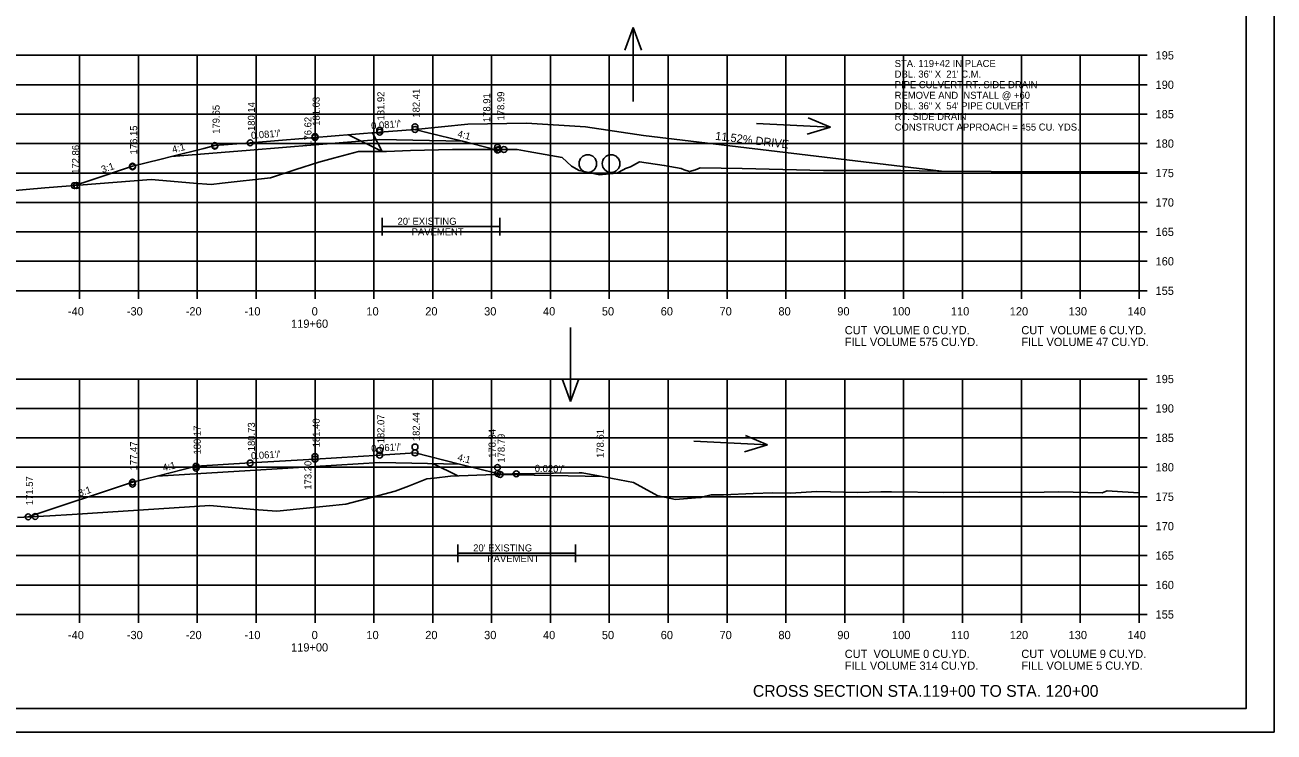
# Model space of a CAD drawing. Extents: x 915787 to 919910, y 133456 to 136717.
# Drawn here: x 916364.7 to 916576.9, y 135802.7 to 135922.9 of the extents above; entities that cross this region are included whole.
import ezdxf

# ---------------------------------------------------------------- set-up
doc = ezdxf.new("R2010")
doc.units = 0
for name, color, linetype in [('R_Axis', 7, 'Continuous'), ('R_Axis Annot', 7, 'Continuous'), ('R_Border', 7, 'Continuous'), ('R_Border Notes', 7, 'Continuous'), ('R_Draft', 7, 'Continuous'), ('R_Drive', 7, 'Continuous'), ('R_Exist Surface', 7, 'Continuous'), ('R_Exist Surface Annot', 7, 'Continuous'), ('R_Fin Surface', 7, 'Continuous'), ('R_Grid', 7, 'Continuous'), ('R_No Plot', 7, 'Continuous'), ('R_Water', 7, 'Continuous'), ('R_Water Annot', 7, 'Continuous'), ('R_Xsect Elev', 7, 'Continuous'), ('R_Xsect Slope', 7, 'Continuous')]:
    doc.layers.add(name, color=color, linetype=linetype)

msp = doc.modelspace()

# ---------------------------------------------------------------- linework, layer by layer
at = {"layer": 'R_Axis'}
for p, q in [((916553.98, 135877.73), (916553.98, 135917.73)), ((916555.38, 135917.73), (916553.98, 135917.73)), ((916555.38, 135912.73), (916553.98, 135912.73)), ((916555.38, 135907.73), (916553.98, 135907.73)), ((916555.38, 135902.73), (916553.98, 135902.73)), ((916555.38, 135897.73), (916553.98, 135897.73)), ((916555.38, 135892.73), (916553.98, 135892.73)), ((916555.38, 135887.73), (916553.98, 135887.73)), ((916555.38, 135882.73), (916553.98, 135882.73)), ((916273.98, 135877.73), (916553.98, 135877.73)), ((916373.98, 135876.33), (916373.98, 135877.73)), ((916383.98, 135876.33), (916383.98, 135877.73)), ((916393.98, 135876.33), (916393.98, 135877.73)), ((916403.98, 135876.33), (916403.98, 135877.73)), ((916413.98, 135876.33), (916413.98, 135877.73)), ((916423.98, 135876.33), (916423.98, 135877.73)), ((916433.98, 135876.33), (916433.98, 135877.73)), ((916443.98, 135876.33), (916443.98, 135877.73)), ((916453.98, 135876.33), (916453.98, 135877.73)), ((916463.98, 135876.33), (916463.98, 135877.73)), ((916473.98, 135876.33), (916473.98, 135877.73)), ((916483.98, 135876.33), (916483.98, 135877.73)), ((916493.98, 135876.33), (916493.98, 135877.73)), ((916503.98, 135876.33), (916503.98, 135877.73)), ((916513.98, 135876.33), (916513.98, 135877.73)), ((916523.98, 135876.33), (916523.98, 135877.73)), ((916533.98, 135876.33), (916533.98, 135877.73)), ((916543.98, 135876.33), (916543.98, 135877.73)), ((916553.98, 135876.33), (916553.98, 135877.73)), ((916555.38, 135877.73), (916553.98, 135877.73)), ((916553.98, 135822.73), (916553.98, 135862.73)), ((916555.38, 135862.73), (916553.98, 135862.73)), ((916555.38, 135857.73), (916553.98, 135857.73)), ((916555.38, 135852.73), (916553.98, 135852.73)), ((916555.38, 135847.73), (916553.98, 135847.73)), ((916555.38, 135842.73), (916553.98, 135842.73)), ((916555.38, 135837.73), (916553.98, 135837.73)), ((916555.38, 135832.73), (916553.98, 135832.73)), ((916555.38, 135827.73), (916553.98, 135827.73)), ((916273.98, 135822.73), (916553.98, 135822.73)), ((916373.98, 135821.33), (916373.98, 135822.73)), ((916383.98, 135821.33), (916383.98, 135822.73)), ((916393.98, 135821.33), (916393.98, 135822.73)), ((916403.98, 135821.33), (916403.98, 135822.73)), ((916413.98, 135821.33), (916413.98, 135822.73)), ((916423.98, 135821.33), (916423.98, 135822.73)), ((916433.98, 135821.33), (916433.98, 135822.73)), ((916443.98, 135821.33), (916443.98, 135822.73)), ((916453.98, 135821.33), (916453.98, 135822.73)), ((916463.98, 135821.33), (916463.98, 135822.73)), ((916473.98, 135821.33), (916473.98, 135822.73)), ((916483.98, 135821.33), (916483.98, 135822.73)), ((916493.98, 135821.33), (916493.98, 135822.73)), ((916503.98, 135821.33), (916503.98, 135822.73)), ((916513.98, 135821.33), (916513.98, 135822.73)), ((916523.98, 135821.33), (916523.98, 135822.73)), ((916533.98, 135821.33), (916533.98, 135822.73)), ((916543.98, 135821.33), (916543.98, 135822.73)), ((916553.98, 135821.33), (916553.98, 135822.73)), ((916555.38, 135822.73), (916553.98, 135822.73))]:
    msp.add_line(p, q, dxfattribs=at)
at = {"layer": 'R_Border'}
for q in [(916572.16, 136012.19), (916255.98, 135806.73)]:
    msp.add_line((916572.16, 135806.73), q, dxfattribs=at)
at = {"layer": 'R_Drive'}
for p, q in [((916439.93, 135906.01), (916430.97, 135905.14)), ((916449.93, 135906.18), (916439.93, 135906.01)), ((916459.91, 135905.56), (916449.93, 135906.18)), ((916469.81, 135904.13), (916459.91, 135905.56)), ((916419.68, 135904.22), (916425.36, 135901.38)), ((916469.81, 135904.13), (916520.4, 135898.06)), ((916434, 135848.37), (916438.22, 135846.26))]:
    msp.add_line(p, q, dxfattribs=at)
at = {"layer": 'R_Exist Surface'}
for points in [[(916361.71, 135894.67), (916368.05, 135895.2), (916386.14, 135896.62), (916393.36, 135896), (916396.31, 135895.77), (916398.21, 135895.98), (916406.44, 135896.91), (916410.71, 135898.3), (916414.61, 135899.56), (916417.12, 135900.24), (916421.36, 135901.39), (916423.59, 135901.41), (916426.12, 135901.41), (916430.23, 135901.53), (916437.32, 135901.72), (916445.81, 135901.73), (916448.33, 135901.71), (916450.2, 135901.36), (916455.97, 135900.35), (916457.56, 135898.89), (916458.83, 135898.13), (916461.83, 135897.53), (916462.32, 135897.44), (916462.83, 135897.46), (916465.24, 135897.71), (916466.46, 135898.35), (916466.74, 135898.47), (916467.55, 135898.8), (916469.13, 135899.62), (916473.3, 135899.03), (916476.16, 135898.5), (916476.68, 135898.29), (916477.63, 135897.98), (916478.62, 135898.28), (916479.39, 135898.59), (916486.56, 135898.48), (916500.36, 135898.18), (916506.22, 135898.15), (916513.52, 135898.15), (916519.76, 135898.07), (916528.86, 135897.96), (916534.17, 135897.95), (916538.54, 135897.94), (916553.98, 135897.97)], [(916363.43, 135839.21), (916368.92, 135839.48), (916372.74, 135839.72), (916396.1, 135841.21), (916403.59, 135840.57), (916407.48, 135840.26), (916412.51, 135840.78), (916419.23, 135841.47), (916424.84, 135842.92), (916427.62, 135843.69), (916429.86, 135844.53), (916432.98, 135845.76), (916434.22, 135845.88), (916437.01, 135846.22), (916447.49, 135846.6), (916448.33, 135846.62), (916454.5, 135846.72), (916458.86, 135846.8), (916459.35, 135846.81), (916462.12, 135846.29), (916468.07, 135845.17), (916471.6, 135843.21), (916472.22, 135842.88), (916472.26, 135842.88), (916475.22, 135842.26), (916479.3, 135842.59), (916479.54, 135842.59), (916479.89, 135842.69), (916481.27, 135843.04), (916483.39, 135843.03), (916488.41, 135843.26), (916491.76, 135843.38), (916494.74, 135843.33), (916499.26, 135843.6), (916506.12, 135843.44), (916510.09, 135843.58), (916511.94, 135843.54), (916520.8, 135843.47), (916526.91, 135843.53), (916535.35, 135843.42), (916540.34, 135843.54), (916547.69, 135843.39), (916548.55, 135843.74), (916551.19, 135843.56), (916553.98, 135843.41)]]:
    msp.add_lwpolyline(points, dxfattribs=at)
at = {"layer": 'R_Exist Surface Annot'}
for p, q in [((916425.36, 135890.13), (916425.36, 135887.13)), ((916425.36, 135888.63), (916445.36, 135888.63)), ((916445.36, 135890.13), (916445.36, 135887.13)), ((916438.22, 135834.63), (916438.22, 135831.63)), ((916458.21, 135834.63), (916458.21, 135831.63)), ((916438.22, 135833.13), (916458.21, 135833.13))]:
    msp.add_line(p, q, dxfattribs=at)
at = {"layer": 'R_Fin Surface'}
for points in [[(916373.1, 135895.59), (916375.75, 135896.48), (916382.97, 135898.89), (916387.87, 135900.11), (916389.57, 135900.53), (916395.11, 135901.92), (916396.97, 135902.39), (916398.48, 135902.51), (916402.97, 135902.87), (916405.74, 135903.09), (916413.97, 135903.76), (916416.74, 135903.98), (916424.97, 135904.66), (916426.48, 135904.78), (916430.97, 135905.14), (916432.99, 135904.64), (916439.04, 135903.12), (916440.55, 135902.75), (916444.97, 135901.64), (916445.02, 135901.66), (916445.21, 135901.72)], [(916389.57, 135900.53), (916402.97, 135901.62), (916413.97, 135902.51), (916424.97, 135903.41), (916439.04, 135903.12)], [(916365.26, 135839.3), (916382.97, 135845.21), (916387.16, 135846.25), (916393.77, 135847.9), (916402.97, 135848.46), (916413.97, 135849.13), (916424.97, 135849.8), (916430.97, 135850.17), (916438.52, 135848.28), (916444.97, 135846.67), (916445.41, 135846.52), (916462.76, 135846.18)], [(916387.16, 135846.25), (916402.97, 135847.21), (916413.97, 135847.88), (916424.97, 135848.55), (916438.52, 135848.28)]]:
    msp.add_lwpolyline(points, dxfattribs=at)
at = {"layer": 'R_Grid'}
for p, q in [((916273.98, 135917.73), (916553.98, 135917.73)), ((916373.98, 135877.73), (916373.98, 135917.73)), ((916383.98, 135877.73), (916383.98, 135917.73)), ((916393.98, 135877.73), (916393.98, 135917.73)), ((916403.98, 135877.73), (916403.98, 135917.73)), ((916413.98, 135877.73), (916413.98, 135917.73)), ((916423.98, 135877.73), (916423.98, 135917.73)), ((916433.98, 135877.73), (916433.98, 135917.73)), ((916443.98, 135877.73), (916443.98, 135917.73)), ((916453.98, 135877.73), (916453.98, 135917.73)), ((916463.98, 135877.73), (916463.98, 135917.73)), ((916473.98, 135877.73), (916473.98, 135917.73)), ((916483.98, 135877.73), (916483.98, 135917.73)), ((916493.98, 135877.73), (916493.98, 135917.73)), ((916503.98, 135877.73), (916503.98, 135917.73)), ((916513.98, 135877.73), (916513.98, 135917.73)), ((916523.98, 135877.73), (916523.98, 135917.73)), ((916533.98, 135877.73), (916533.98, 135917.73)), ((916543.98, 135877.73), (916543.98, 135917.73)), ((916553.98, 135877.73), (916553.98, 135917.73)), ((916273.98, 135912.73), (916553.98, 135912.73)), ((916273.98, 135907.73), (916553.98, 135907.73)), ((916273.98, 135902.73), (916553.98, 135902.73)), ((916273.98, 135897.73), (916553.98, 135897.73)), ((916273.98, 135892.73), (916553.98, 135892.73)), ((916273.98, 135887.73), (916553.98, 135887.73)), ((916273.98, 135882.73), (916553.98, 135882.73)), ((916273.98, 135877.73), (916553.98, 135877.73)), ((916273.98, 135862.73), (916553.98, 135862.73)), ((916373.98, 135822.73), (916373.98, 135862.73)), ((916383.98, 135822.73), (916383.98, 135862.73)), ((916393.98, 135822.73), (916393.98, 135862.73)), ((916403.98, 135822.73), (916403.98, 135862.73)), ((916413.98, 135822.73), (916413.98, 135862.73)), ((916423.98, 135822.73), (916423.98, 135862.73)), ((916433.98, 135822.73), (916433.98, 135862.73)), ((916443.98, 135822.73), (916443.98, 135862.73)), ((916453.98, 135822.73), (916453.98, 135862.73)), ((916463.98, 135822.73), (916463.98, 135862.73)), ((916473.98, 135822.73), (916473.98, 135862.73)), ((916483.98, 135822.73), (916483.98, 135862.73)), ((916493.98, 135822.73), (916493.98, 135862.73)), ((916503.98, 135822.73), (916503.98, 135862.73)), ((916513.98, 135822.73), (916513.98, 135862.73)), ((916523.98, 135822.73), (916523.98, 135862.73)), ((916533.98, 135822.73), (916533.98, 135862.73)), ((916543.98, 135822.73), (916543.98, 135862.73)), ((916553.98, 135822.73), (916553.98, 135862.73)), ((916273.98, 135857.73), (916553.98, 135857.73)), ((916273.98, 135852.73), (916553.98, 135852.73)), ((916273.98, 135847.73), (916553.98, 135847.73)), ((916273.98, 135842.73), (916553.98, 135842.73)), ((916273.98, 135837.73), (916553.98, 135837.73)), ((916273.98, 135832.73), (916553.98, 135832.73)), ((916273.98, 135827.73), (916553.98, 135827.73)), ((916273.98, 135822.73), (916553.98, 135822.73))]:
    msp.add_line(p, q, dxfattribs=at)
at = {"layer": 'R_No Plot'}
msp.add_line((916243.57, 135802.75), (916576.91, 135802.75), dxfattribs=at)
for points in [[(916243.57, 136016.09), (916576.91, 136016.09), (916576.91, 135802.75), (916243.57, 135802.75)], [(916489.9, 136012.19), (916489.9, 136002.31), (916525.63, 136002.31), (916525.63, 135999.39), (916548.83, 135999.39), (916548.83, 135976.18), (916572.16, 135976.18), (916572.16, 135806.73), (916255.98, 135806.73), (916255.98, 136012.19)]]:
    msp.add_lwpolyline(points, close=True, dxfattribs=at)
for centre in [(916424.97, 135905.01), (916430.97, 135905.59), (916430.97, 135905.14), (916402.97, 135902.87), (916402.97, 135902.87), (916413.97, 135903.94), (916413.97, 135903.76), (916424.97, 135904.66), (916396.97, 135902.39), (916396.97, 135902.29), (916444.97, 135902.09), (916444.97, 135901.64), (916445.21, 135901.72), (916446.08, 135901.72), (916382.97, 135898.89), (916382.97, 135898.79), (916373.1, 135895.59), (916373.48, 135895.62), (916424.97, 135850.6), (916424.97, 135849.8), (916430.97, 135851.18), (916430.97, 135850.17), (916393.77, 135847.9), (916402.97, 135848.46), (916402.97, 135848.46), (916413.97, 135849.53), (916413.97, 135849.13), (916444.97, 135847.68), (916393.77, 135847.57), (916444.97, 135846.67), (916445.41, 135846.52), (916448.18, 135846.61), (916382.97, 135845.21), (916382.97, 135844.87), (916365.26, 135839.3), (916366.44, 135839.36)]:
    msp.add_circle(centre, 0.5, dxfattribs=at)
at = {"layer": 'R_Water'}
for p, q in [((916423.77, 135904.56), (916425.36, 135901.38)), ((916445.41, 135846.52), (916462.76, 135846.18))]:
    msp.add_line(p, q, dxfattribs=at)
for centre in [(916460.33, 135899.33), (916464.28, 135899.33)]:
    msp.add_circle(centre, 1.5, dxfattribs=at)
at = {"layer": 'R_Water Annot'}
for p, q in [((916468.04, 135922.45), (916466.64, 135918.61)), ((916468.04, 135909.88), (916468.04, 135922.45)), ((916468.04, 135922.45), (916469.44, 135918.61)), ((916488.98, 135906.13), (916501.53, 135905.53)), ((916501.53, 135905.53), (916497.62, 135904.32)), ((916501.53, 135905.53), (916497.76, 135907.11)), ((916457.38, 135871.49), (916457.38, 135858.92)), ((916457.38, 135858.92), (916455.98, 135862.77)), ((916457.38, 135858.92), (916458.78, 135862.77)), ((916490.88, 135851.55), (916487.11, 135853.14)), ((916478.33, 135852.15), (916490.88, 135851.55)), ((916490.88, 135851.55), (916486.97, 135850.34))]:
    msp.add_line(p, q, dxfattribs=at)

# ---------------------------------------------------------------- texts
at = {"layer": 'R_Axis Annot'}
for s, p in [('195', (916556.78, 135917.03)), ('190', (916556.78, 135912.03)), ('185', (916556.78, 135907.03)), ('180', (916556.78, 135902.03)), ('175', (916556.78, 135897.03)), ('170', (916556.78, 135892.03)), ('165', (916556.78, 135887.03)), ('160', (916556.78, 135882.03)), ('155', (916556.78, 135877.03)), ('-40', (916372.01, 135873.53)), ('-30', (916382.01, 135873.53)), ('-20', (916392.01, 135873.53)), ('-10', (916402.01, 135873.53)), ('0', (916413.41, 135873.53)), ('10', (916422.71, 135873.53)), ('20', (916432.71, 135873.53)), ('30', (916442.71, 135873.53)), ('40', (916452.71, 135873.53)), ('50', (916462.71, 135873.53)), ('60', (916472.71, 135873.53)), ('70', (916482.71, 135873.53)), ('80', (916492.71, 135873.53)), ('90', (916502.71, 135873.53)), ('100', (916512.01, 135873.53)), ('110', (916522.01, 135873.53)), ('120', (916532.01, 135873.53)), ('130', (916542.01, 135873.53)), ('140', (916552.01, 135873.53)), ('119+60', (916409.91, 135871.43)), ('195', (916556.78, 135862.03)), ('190', (916556.78, 135857.03)), ('185', (916556.78, 135852.03)), ('180', (916556.78, 135847.03)), ('175', (916556.78, 135842.03)), ('170', (916556.78, 135837.03)), ('165', (916556.78, 135832.03)), ('160', (916556.78, 135827.03)), ('155', (916556.78, 135822.03)), ('-40', (916372.01, 135818.53)), ('-30', (916382.01, 135818.53)), ('-20', (916392.01, 135818.53)), ('-10', (916402.01, 135818.53)), ('0', (916413.41, 135818.53)), ('10', (916422.71, 135818.53)), ('20', (916432.71, 135818.53)), ('30', (916442.71, 135818.53)), ('40', (916452.71, 135818.53)), ('50', (916462.71, 135818.53)), ('60', (916472.71, 135818.53)), ('70', (916482.71, 135818.53)), ('80', (916492.71, 135818.53)), ('90', (916502.71, 135818.53)), ('100', (916512.01, 135818.53)), ('110', (916522.01, 135818.53)), ('120', (916532.01, 135818.53)), ('130', (916542.01, 135818.53)), ('140', (916552.01, 135818.53)), ('119+00', (916409.91, 135816.43))]:
    msp.add_text(s, height=1.4, dxfattribs=at).set_placement(p)
at = {"layer": 'R_Border Notes'}
for s, p in [('CUT  VOLUME 0 CU.YD.', (916503.98, 135870.33)), ('CUT  VOLUME 6 CU.YD.', (916533.98, 135870.33)), ('FILL VOLUME 575 CU.YD.', (916503.98, 135868.33)), ('FILL VOLUME 47 CU.YD.', (916533.98, 135868.33)), ('CUT  VOLUME 0 CU.YD.', (916503.98, 135815.33)), ('CUT  VOLUME 9 CU.YD.', (916533.98, 135815.33)), ('FILL VOLUME 314 CU.YD.', (916503.98, 135813.33)), ('FILL VOLUME 5 CU.YD.', (916533.98, 135813.33))]:
    msp.add_text(s, height=1.4, dxfattribs=at).set_placement(p)
at = {"layer": 'R_Draft'}
msp.add_text('CROSS SECTION STA.119+00 TO STA. 120+00', height=2, dxfattribs=at).set_placement((916488.37, 135808.73))
at = {"layer": 'R_Drive'}
msp.add_text('11.52% DRIVE', height=1.4, rotation=353.1572, dxfattribs=at).set_placement((916481.92, 135903.38))
at = {"layer": 'R_Exist Surface Annot'}
for s, p in [("20' EXISTING", (916428, 135888.93)), ('PAVEMENT', (916430.4, 135887.13)), ("20' EXISTING", (916440.85, 135833.43)), ('PAVEMENT', (916443.26, 135831.63))]:
    msp.add_text(s, height=1.2, dxfattribs=at).set_placement(p)
at = {"layer": 'R_Water Annot'}
for s, p in [('STA. 119+42 IN PLACE', (916512.46, 135915.74)), ('DBL. 36" X  21\' C.M.   ', (916512.46, 135913.94)), ('PIPE CULVERT RT. SIDE DRAIN', (916512.46, 135912.14)), ('REMOVE AND INSTALL @ +60', (916512.46, 135910.34)), ('DBL. 36" X  54\' PIPE CULVERT', (916512.46, 135908.54)), ('RT. SIDE DRAIN', (916512.46, 135906.74)), ('CONSTRUCT APPROACH = 455 CU. YDS.', (916512.46, 135904.94))]:
    msp.add_text(s, height=1.2, dxfattribs=at).set_placement(p)
at = {"layer": 'R_Xsect Elev'}
for s, p in [('182.41', (916431.77, 135907.14)), ('180.14', (916403.77, 135904.87)), ('181.03', (916414.77, 135905.76)), ('181.92', (916425.77, 135906.66)), ('178.91', (916443.75, 135906.38)), ('178.99', (916446.14, 135906.66)), ('179.65', (916397.77, 135904.39)), ('176.15', (916383.77, 135900.89)), ('176.62', (916413.38, 135902.36)), ('172.86', (916373.9, 135897.59)), ('182.07', (916425.77, 135851.8)), ('182.44', (916431.77, 135852.17)), ('180.17', (916394.57, 135849.9)), ('180.73', (916403.77, 135850.46)), ('181.40', (916414.77, 135851.13)), ('178.94', (916444.66, 135849.34)), ('178.79', (916446.21, 135848.52)), ('178.61', (916463.04, 135849.32)), ('177.47', (916383.77, 135847.21)), ('173.20', (916413.38, 135843.93)), ('171.57', (916366.06, 135841.3))]:
    msp.add_text(s, height=1.2, rotation=90, dxfattribs=at).set_placement(p)
at = {"layer": 'R_Xsect Slope'}
for s, rotation, p in [("0.081'/'", 4.6368, (916423.56, 135905.14)), ("0.081'/'", 4.6368, (916403.15, 135903.51)), ('4:1', 345.9637, (916438.09, 135903.88)), ('4:1', 14.0363, (916389.85, 135901.12)), ('3:1', 18.435, (916377.88, 135897.71)), ("0.061'/'", 3.4841, (916403.14, 135849.08)), ("0.061'/'", 3.4841, (916423.57, 135850.32)), ('4:1', 14.0362, (916388.25, 135847.04)), ('4:1', 345.9638, (916438.1, 135848.9)), ("0.020'/'", 358.8542, (916451.3, 135846.96)), ('3:1', 18.4349, (916373.96, 135842.73))]:
    msp.add_text(s, height=1.2, rotation=rotation, dxfattribs=at).set_placement(p)

doc.saveas('drawing.dxf')
